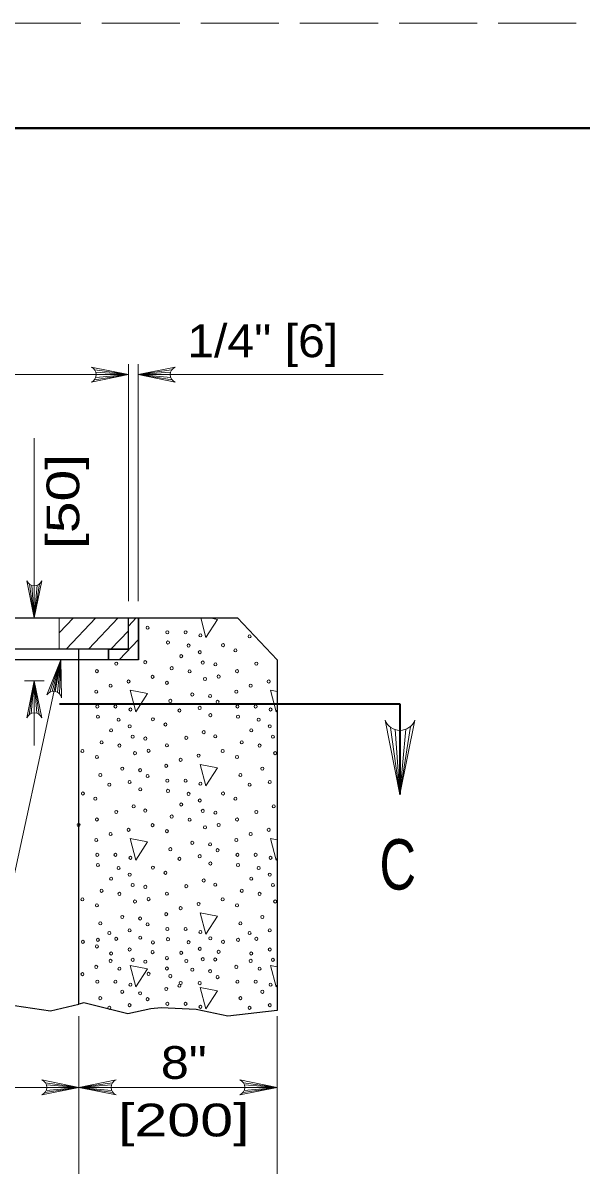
# Model space of a CAD drawing. Extents: x -410.5 to -376.5, y 1617.6 to 1661.6.
# Drawn here: x -391.36 to -388.7, y 1656.07 to 1661.56 of the extents above; entities that cross this region are included whole.
import ezdxf
from ezdxf.enums import TextEntityAlignment as Align

# ---------------------------------------------------------------- set-up
doc = ezdxf.new("R2010")
doc.units = 0
doc.header["$LTSCALE"] = 0.062
doc.linetypes.add('LONG_DASHED', pattern=[7.5, 6, -1.5])
doc.layers.add('1', color=7, linetype='Continuous', lineweight=13)

msp = doc.modelspace()

# ---------------------------------------------------------------- linework, layer by layer
at = {"layer": '1', "lineweight": 25}
for p, q in [((-408.45475, 1661.06183), (-376.95475, 1661.06183)), ((-391.90558, 1658.72817), (-390.8125, 1658.72817)), ((-390.85967, 1658.57825), (-390.85967, 1658.72817)), ((-390.8125, 1658.52825), (-390.8125, 1658.72817)), ((-390.85967, 1658.57825), (-391.4025, 1658.57825)), ((-390.8125, 1658.52825), (-391.4025, 1658.52825)), ((-391.09567, 1656.88817), (-391.09567, 1658.57825)), ((-390.95408, 1658.57825), (-390.95408, 1658.52825))]:
    msp.add_line(p, q, dxfattribs=at)
at = {"layer": '1'}
for p, q in [((-391.01992, 1659.90942), (-390.85967, 1659.887)), ((-390.85967, 1658.80683), (-390.85967, 1659.937)), ((-390.65383, 1659.90942), (-390.81408, 1659.887)), ((-390.81375, 1658.80683), (-390.81375, 1659.937)), ((-392.77792, 1659.887), (-390.85967, 1659.887)), ((-392.03408, 1659.887), (-390.86258, 1659.887)), ((-391.02183, 1659.86225), (-390.85967, 1659.887)), ((-391.01567, 1659.87258), (-390.85967, 1659.887)), ((-391.0145, 1659.89833), (-390.85967, 1659.887)), ((-391.01283, 1659.887), (-390.85967, 1659.887)), ((-390.65925, 1659.89833), (-390.81408, 1659.887)), ((-390.81408, 1659.887), (-389.647, 1659.887)), ((-390.66092, 1659.887), (-390.81408, 1659.887)), ((-390.65808, 1659.87258), (-390.81408, 1659.887)), ((-390.65192, 1659.86225), (-390.81408, 1659.887)), ((-391.30808, 1658.72817), (-391.30808, 1659.58383)), ((-391.3305, 1658.88833), (-391.30808, 1658.72817)), ((-391.31942, 1658.88292), (-391.30808, 1658.72817)), ((-391.28325, 1658.89025), (-391.30808, 1658.72817)), ((-391.29367, 1658.88417), (-391.30808, 1658.72817)), ((-391.30808, 1658.88133), (-391.30808, 1658.72817)), ((-391.30808, 1658.72817), (-391.11925, 1658.72817)), ((-391.19008, 1658.57825), (-391.19008, 1658.72817)), ((-391.19008, 1658.65608), (-391.12208, 1658.72808)), ((-391.15675, 1658.57833), (-391.01525, 1658.72808)), ((-391.05, 1658.57833), (-390.9085, 1658.72808)), ((-390.85967, 1658.6885), (-390.82225, 1658.72817)), ((-390.51508, 1658.72808), (-390.49042, 1658.63442)), ((-390.94325, 1658.57833), (-390.85967, 1658.66675)), ((-390.90425, 1658.52825), (-390.8125, 1658.62542)), ((-391.23483, 1658.37333), (-391.18092, 1658.52825)), ((-391.22358, 1658.3775), (-391.18092, 1658.52825)), ((-391.20883, 1658.37767), (-391.18092, 1658.52825)), ((-391.198, 1658.374), (-391.18092, 1658.52825)), ((-391.18808, 1658.36658), (-391.18092, 1658.52825)), ((-391.35525, 1658.42833), (-391.26083, 1658.42833)), ((-391.33283, 1658.26617), (-391.30808, 1658.42833)), ((-391.3225, 1658.27233), (-391.30808, 1658.42833)), ((-391.30808, 1658.42833), (-391.30808, 1658.11933)), ((-391.30808, 1658.27517), (-391.30808, 1658.42833)), ((-391.29675, 1658.2735), (-391.30808, 1658.42833)), ((-391.28567, 1658.26808), (-391.30808, 1658.42833)), ((-390.15167, 1658.37717), (-390.18367, 1658.3835)), ((-389.61125, 1658.2065), (-389.56642, 1657.886)), ((-389.51692, 1658.21033), (-389.56642, 1657.886)), ((-389.53767, 1658.198), (-389.56642, 1657.886)), ((-389.58908, 1658.19567), (-389.56642, 1657.886)), ((-389.56642, 1658.19233), (-389.56642, 1657.886)), ((-390.15175, 1657.6705), (-390.18367, 1657.67675)), ((-390.15167, 1657.06608), (-390.18367, 1657.07225)), ((-391.09567, 1656.07967), (-391.09567, 1656.82983)), ((-390.15167, 1656.07967), (-390.15167, 1656.82983)), ((-391.25592, 1656.51367), (-391.09567, 1656.49125)), ((-391.2505, 1656.50258), (-391.09567, 1656.49125)), ((-390.93542, 1656.51367), (-391.09567, 1656.49125)), ((-390.94083, 1656.50258), (-391.09567, 1656.49125)), ((-390.31192, 1656.51367), (-390.15167, 1656.49125)), ((-390.3065, 1656.50258), (-390.15167, 1656.49125)), ((-392.1675, 1656.49125), (-391.09567, 1656.49125)), ((-391.25783, 1656.4665), (-391.09567, 1656.49125)), ((-391.25167, 1656.47683), (-391.09567, 1656.49125)), ((-391.24883, 1656.49125), (-391.09567, 1656.49125)), ((-390.9425, 1656.49125), (-391.09567, 1656.49125)), ((-390.93967, 1656.47683), (-391.09567, 1656.49125)), ((-390.93358, 1656.4665), (-391.09567, 1656.49125)), ((-390.31383, 1656.4665), (-390.15167, 1656.49125)), ((-390.30767, 1656.47683), (-390.15167, 1656.49125)), ((-390.30483, 1656.49125), (-390.15167, 1656.49125))]:
    msp.add_line(p, q, dxfattribs=at)
at = {"layer": '1', "lineweight": 35}
for p, q in [((-391.188, 1658.31867), (-389.56642, 1658.31867)), ((-389.56642, 1658.31867), (-389.56642, 1657.886))]:
    msp.add_line(p, q, dxfattribs=at)
at = {"layer": '1', "linetype": 'LONG_DASHED'}
msp.add_lwpolyline([(-410.45475, 1639.56183), (-376.45475, 1639.56183), (-376.45475, 1661.56183), (-410.45475, 1661.56183)], close=True, dxfattribs=at)
at = {"layer": '1', "lineweight": 40}
msp.add_lwpolyline([(-408.45475, 1661.06183), (-376.95475, 1661.06183), (-376.95475, 1640.06183), (-408.45475, 1640.06183)], close=True, dxfattribs=at)
msp.add_lwpolyline([(-408.45475, 1661.06183), (-376.95475, 1661.06183), (-376.95475, 1640.06183), (-408.45475, 1640.06183)], close=True, dxfattribs=at)
at = {"layer": '1'}
for points in [[(-391.03667, 1659.85158), (-390.85967, 1659.887), (-391.03667, 1659.92242)], [(-390.63708, 1659.85158), (-390.81408, 1659.887), (-390.63708, 1659.92242)], [(-391.27267, 1658.90517), (-391.30808, 1658.72817), (-391.3435, 1658.90517)], [(-390.49042, 1658.63442), (-390.4355, 1658.72092), (-390.47292, 1658.72817)], [(-391.18092, 1658.52825), (-391.4595, 1657.24567), (-391.65833, 1657.24567)], [(-391.248, 1658.36067), (-391.18092, 1658.52825), (-391.17842, 1658.34775)], [(-391.3435, 1658.25133), (-391.30808, 1658.42833), (-391.27267, 1658.25133)], [(-390.18367, 1658.3835), (-390.15667, 1658.28108), (-390.15158, 1658.28892)], [(-389.49567, 1658.24), (-389.56642, 1657.886), (-389.63725, 1658.24)], [(-390.18367, 1657.67675), (-390.15667, 1657.57442), (-390.15167, 1657.58217)], [(-390.18367, 1657.07225), (-390.15667, 1656.96983), (-390.15167, 1656.97792)], [(-391.27267, 1656.45583), (-391.09567, 1656.49125), (-391.27267, 1656.52667)], [(-390.91867, 1656.45583), (-391.09567, 1656.49125), (-390.91867, 1656.52667)], [(-390.32867, 1656.45583), (-390.15167, 1656.49125), (-390.32867, 1656.52667)], [(-391.09567, 1656.49125), (-390.35633, 1656.49125), (-390.15167, 1656.49125)]]:
    msp.add_lwpolyline(points, dxfattribs=at)
at = {"layer": '1', "lineweight": 25}
msp.add_lwpolyline([(-390.95408, 1658.57825), (-390.85967, 1658.57825), (-390.85967, 1658.72817), (-390.8125, 1658.72817), (-390.8125, 1658.52825), (-390.95408, 1658.52825)], close=True, dxfattribs=at)
for points in [[(-390.8125, 1658.72817), (-390.3405, 1658.72817), (-390.15167, 1658.52825), (-390.15167, 1656.858)], [(-393.83325, 1656.87183), (-393.68983, 1656.83983), (-393.57033, 1656.87083), (-393.40175, 1656.85217), (-393.34308, 1656.855), (-393.2425, 1656.88925), (-393.18192, 1656.882), (-393.12783, 1656.87983), (-392.90825, 1656.84083), (-392.75167, 1656.88892), (-392.54808, 1656.86817), (-392.37933, 1656.90217), (-392.26933, 1656.909), (-392.08858, 1656.85375), (-391.91983, 1656.88475), (-391.69733, 1656.84675), (-391.53892, 1656.88275), (-391.48967, 1656.89375), (-391.23017, 1656.85558), (-391.09567, 1656.88817)], [(-390.15167, 1656.858), (-390.38608, 1656.83008), (-390.53658, 1656.86183), (-390.70333, 1656.87042), (-390.75258, 1656.86542), (-390.86258, 1656.8415), (-391.07275, 1656.89367), (-391.09567, 1656.88817)]]:
    msp.add_lwpolyline(points, dxfattribs=at)
at = {"layer": '1'}
for points in [[(-390.85117, 1658.3835), (-390.82417, 1658.28108), (-390.76917, 1658.3675)], [(-390.51742, 1658.03008), (-390.49042, 1657.92767), (-390.4355, 1658.01408)], [(-390.85117, 1657.67675), (-390.82417, 1657.57442), (-390.76917, 1657.66083)], [(-390.51742, 1657.32342), (-390.49042, 1657.221), (-390.4355, 1657.30742)], [(-390.85117, 1657.07225), (-390.82417, 1656.96983), (-390.76917, 1657.05625)], [(-390.51742, 1656.96708), (-390.49042, 1656.86467), (-390.4355, 1656.95117)]]:
    msp.add_lwpolyline(points, close=True, dxfattribs=at)
for centre, radius, start, end in [((-391.05096, 1659.88703), 0.0382, 292.08605, 67.91218), ((-390.62279, 1659.88703), 0.0382, 112.08782, 247.91395), ((-391.30811, 1658.91942), 0.0382, 202.08782, 337.91395), ((-391.21579, 1658.34016), 0.0382, 11.58076, 147.40689), ((-391.30803, 1658.23701), 0.0382, 22.08782, 157.91395), ((-389.56653, 1658.26863), 0.0764, 202.08782, 337.91395), ((-391.28698, 1656.49131), 0.0382, 292.08605, 67.91218), ((-390.90439, 1656.49131), 0.0382, 112.08782, 247.91395), ((-390.34298, 1656.49131), 0.0382, 292.08605, 67.91218)]:
    msp.add_arc(centre, radius, start, end, dxfattribs=at)
for centre, major_axis in [((-390.76879, 1658.68111), (0, -0.00756)), ((-390.67417, 1658.65914), (0, -0.00756)), ((-390.58762, 1658.65914), (0, 0.00756)), ((-390.51648, 1658.64483), (0, -0.00756)), ((-390.28301, 1658.64006), (0, 0.00756)), ((-390.6715, 1658.6105), (0, -0.00756)), ((-390.57321, 1658.59618), (0, 0.00756)), ((-390.40923, 1658.59807), (0, -0.00756)), ((-390.34977, 1658.57328), (0, -0.00756)), ((-390.60842, 1658.5456), (0, 0.00756)), ((-390.52009, 1658.56468), (0, 0.00756)), ((-391.01004, 1658.47398), (0, -0.00756)), ((-390.91782, 1658.51003), (0, -0.00756)), ((-390.77992, 1658.51668), (0, -0.00756)), ((-390.65376, 1658.48806), (0, 0.00756)), ((-390.56876, 1658.4731), (0, 0.00756)), ((-390.50563, 1658.51509), (0, 0.00756)), ((-390.44527, 1658.50643), (0, -0.00756)), ((-390.34253, 1658.47398), (0, -0.00756)), ((-390.25031, 1658.51003), (0, -0.00756)), ((-390.85924, 1658.42505), (0, -0.00756)), ((-390.74482, 1658.44701), (0, 0.00756)), ((-390.67629, 1658.41839), (0, 0.00756)), ((-390.49489, 1658.43682), (0, 0.00756)), ((-390.42998, 1658.44831), (0, -0.00756)), ((-390.19173, 1658.42505), (0, -0.00756)), ((-391.01332, 1658.3764), (0, -0.00756)), ((-390.9449, 1658.40502), (0, -0.00756)), ((-390.55552, 1658.36309), (0, 0.00756)), ((-390.47047, 1658.35573), (0, 0.00756)), ((-390.34582, 1658.3764), (0, -0.00756)), ((-390.2774, 1658.40502), (0, -0.00756)), ((-391.00793, 1658.30579), (0, -0.00756)), ((-390.92138, 1658.30579), (0, 0.00756)), ((-390.66005, 1658.33253), (0, 0.00756)), ((-390.52037, 1658.29914), (0, 0.00756)), ((-390.43504, 1658.32776), (0, -0.00756)), ((-390.34042, 1658.30579), (0, -0.00756)), ((-390.25387, 1658.30579), (0, 0.00756)), ((-391.00526, 1658.25715), (0, -0.00756)), ((-390.85023, 1658.29148), (0, -0.00756)), ((-390.74298, 1658.24472), (0, -0.00756)), ((-390.61677, 1658.28671), (0, 0.00756)), ((-390.46958, 1658.26445), (0, -0.00756)), ((-390.33775, 1658.25715), (0, -0.00756)), ((-390.18272, 1658.29148), (0, -0.00756)), ((-390.94218, 1658.19225), (0, 0.00756)), ((-390.90697, 1658.24283), (0, 0.00756)), ((-390.85385, 1658.21133), (0, 0.00756)), ((-390.68352, 1658.21993), (0, -0.00756)), ((-390.27467, 1658.19225), (0, 0.00756)), ((-390.23946, 1658.24283), (0, 0.00756)), ((-390.18634, 1658.21133), (0, 0.00756)), ((-390.98751, 1658.13471), (0, 0.00756)), ((-390.83938, 1658.16174), (0, 0.00756)), ((-390.77903, 1658.15308), (0, -0.00756)), ((-390.58406, 1658.15668), (0, -0.00756)), ((-390.50112, 1658.18335), (0, -0.00756)), ((-390.44616, 1658.16333), (0, -0.00756)), ((-390.32001, 1658.13471), (0, 0.00756)), ((-390.17187, 1658.16174), (0, 0.00756)), ((-391.07857, 1658.09366), (0, 0.00756)), ((-390.90252, 1658.11975), (0, 0.00756)), ((-390.82865, 1658.08347), (0, 0.00756)), ((-390.76373, 1658.09496), (0, -0.00756)), ((-390.67629, 1658.12063), (0, -0.00756)), ((-390.41106, 1658.09366), (0, 0.00756)), ((-390.23501, 1658.11975), (0, 0.00756)), ((-390.16114, 1658.08347), (0, 0.00756)), ((-391.01004, 1658.06504), (0, 0.00756)), ((-390.61115, 1658.05167), (0, -0.00756)), ((-390.52549, 1658.0717), (0, -0.00756)), ((-390.34253, 1658.06504), (0, 0.00756)), ((-390.9938, 1657.97918), (0, 0.00756)), ((-390.88928, 1658.00974), (0, 0.00756)), ((-390.80423, 1658.00238), (0, 0.00756)), ((-390.76879, 1657.97441), (0, -0.00756)), ((-390.67957, 1658.02305), (0, -0.00756)), ((-390.32629, 1657.97918), (0, 0.00756)), ((-390.22177, 1658.00974), (0, 0.00756)), ((-390.95052, 1657.93336), (0, 0.00756)), ((-390.85412, 1657.94579), (0, 0.00756)), ((-390.67417, 1657.95244), (0, -0.00756)), ((-390.58762, 1657.95244), (0, 0.00756)), ((-390.51648, 1657.93813), (0, -0.00756)), ((-390.28301, 1657.93336), (0, 0.00756)), ((-390.18662, 1657.94579), (0, 0.00756)), ((-391.07674, 1657.89137), (0, -0.00756)), ((-391.01727, 1657.86658), (0, -0.00756)), ((-390.80334, 1657.9111), (0, -0.00756)), ((-390.6715, 1657.9038), (0, -0.00756)), ((-390.57321, 1657.88949), (0, 0.00756)), ((-390.40923, 1657.89137), (0, -0.00756)), ((-390.34977, 1657.86658), (0, -0.00756)), ((-390.83488, 1657.83), (0, -0.00756)), ((-390.77992, 1657.80998), (0, -0.00756)), ((-390.60842, 1657.8389), (0, 0.00756)), ((-390.52009, 1657.85798), (0, 0.00756)), ((-390.50563, 1657.80839), (0, 0.00756)), ((-390.16737, 1657.83), (0, -0.00756)), ((-391.01004, 1657.76728), (0, -0.00756)), ((-390.91782, 1657.80333), (0, -0.00756)), ((-390.65376, 1657.78136), (0, 0.00756)), ((-390.56876, 1657.7664), (0, 0.00756)), ((-390.44527, 1657.79973), (0, -0.00756)), ((-390.34253, 1657.76728), (0, -0.00756)), ((-390.25031, 1657.80333), (0, -0.00756)), ((-391.09749, 1657.74161), (0, -0.00756)), ((-390.9449, 1657.69832), (0, -0.00756)), ((-390.85924, 1657.71835), (0, -0.00756)), ((-390.74482, 1657.74031), (0, 0.00756)), ((-390.67629, 1657.71169), (0, 0.00756)), ((-390.49489, 1657.73012), (0, 0.00756)), ((-390.42998, 1657.74161), (0, -0.00756)), ((-390.2774, 1657.69832), (0, -0.00756)), ((-390.19173, 1657.71835), (0, -0.00756)), ((-391.01332, 1657.6697), (0, -0.00756)), ((-390.55552, 1657.65639), (0, 0.00756)), ((-390.47047, 1657.64903), (0, 0.00756)), ((-390.34582, 1657.6697), (0, -0.00756)), ((-391.00793, 1657.59909), (0, -0.00756)), ((-390.92138, 1657.59909), (0, 0.00756)), ((-390.85023, 1657.58478), (0, -0.00756)), ((-390.66005, 1657.62583), (0, 0.00756)), ((-390.52037, 1657.59244), (0, 0.00756)), ((-390.43504, 1657.62106), (0, -0.00756)), ((-390.34042, 1657.59909), (0, -0.00756)), ((-390.25387, 1657.59909), (0, 0.00756)), ((-390.18272, 1657.58478), (0, -0.00756)), ((-391.00526, 1657.55045), (0, -0.00756)), ((-390.90697, 1657.53614), (0, 0.00756)), ((-390.74298, 1657.53802), (0, -0.00756)), ((-390.61677, 1657.58001), (0, 0.00756)), ((-390.46958, 1657.55775), (0, -0.00756)), ((-390.33775, 1657.55045), (0, -0.00756)), ((-390.23946, 1657.53614), (0, 0.00756)), ((-390.94218, 1657.48555), (0, 0.00756)), ((-390.85385, 1657.50463), (0, 0.00756)), ((-390.68352, 1657.51323), (0, -0.00756)), ((-390.50112, 1657.47665), (0, -0.00756)), ((-390.27467, 1657.48555), (0, 0.00756)), ((-390.18634, 1657.50463), (0, 0.00756)), ((-390.98751, 1657.42801), (0, 0.00756)), ((-390.83938, 1657.45504), (0, 0.00756)), ((-390.77903, 1657.44638), (0, -0.00756)), ((-390.58406, 1657.44998), (0, -0.00756)), ((-390.44616, 1657.45663), (0, -0.00756)), ((-390.32001, 1657.42801), (0, 0.00756)), ((-390.17187, 1657.45504), (0, 0.00756)), ((-391.07857, 1657.38696), (0, 0.00756)), ((-390.90252, 1657.41305), (0, 0.00756)), ((-390.82865, 1657.37677), (0, 0.00756)), ((-390.76373, 1657.38826), (0, -0.00756)), ((-390.67629, 1657.41394), (0, -0.00756)), ((-390.52549, 1657.365), (0, -0.00756)), ((-390.41106, 1657.38696), (0, 0.00756)), ((-390.23501, 1657.41305), (0, 0.00756)), ((-390.16114, 1657.37677), (0, 0.00756)), ((-391.01004, 1657.35834), (0, 0.00756)), ((-390.67957, 1657.31635), (0, -0.00756)), ((-390.61115, 1657.34497), (0, -0.00756)), ((-390.34253, 1657.35834), (0, 0.00756)), ((-390.9938, 1657.27248), (0, 0.00756)), ((-390.88928, 1657.30304), (0, 0.00756)), ((-390.80423, 1657.29568), (0, 0.00756)), ((-390.76879, 1657.26771), (0, -0.00756)), ((-390.32629, 1657.27248), (0, 0.00756)), ((-390.22177, 1657.30304), (0, 0.00756)), ((-390.95052, 1657.22666), (0, 0.00756)), ((-390.85412, 1657.23909), (0, 0.00756)), ((-390.80334, 1657.2044), (0, -0.00756)), ((-390.67417, 1657.24574), (0, -0.00756)), ((-390.58762, 1657.24574), (0, 0.00756)), ((-390.51648, 1657.23143), (0, -0.00756)), ((-390.46958, 1657.20143), (0, -0.00756)), ((-390.28301, 1657.22666), (0, 0.00756)), ((-390.18662, 1657.23909), (0, 0.00756)), ((-391.07674, 1657.18467), (0, -0.00756)), ((-391.01004, 1657.16278), (0, -0.00756)), ((-391.00526, 1657.19412), (0, -0.00756)), ((-390.91782, 1657.19882), (0, -0.00756)), ((-390.85385, 1657.14831), (0, 0.00756)), ((-390.74299, 1657.1817), (0, -0.00756)), ((-390.6715, 1657.1971), (0, -0.00756)), ((-390.57321, 1657.18279), (0, 0.00756)), ((-390.52009, 1657.15128), (0, 0.00756)), ((-390.40923, 1657.18467), (0, -0.00756)), ((-390.33775, 1657.19412), (0, -0.00756)), ((-390.25031, 1657.19882), (0, -0.00756)), ((-390.18634, 1657.14831), (0, 0.00756)), ((-390.94491, 1657.09382), (0, -0.00756)), ((-390.94218, 1657.12923), (0, 0.00756)), ((-390.83938, 1657.09872), (0, 0.00756)), ((-390.74482, 1657.13581), (0, 0.00756)), ((-390.67629, 1657.10719), (0, 0.00756)), ((-390.60842, 1657.1322), (0, 0.00756)), ((-390.58406, 1657.09366), (0, -0.00756)), ((-390.50563, 1657.10169), (0, 0.00756)), ((-390.44617, 1657.10031), (0, -0.00756)), ((-390.42998, 1657.1371), (0, -0.00756)), ((-390.2774, 1657.09382), (0, -0.00756)), ((-390.27467, 1657.12923), (0, 0.00756)), ((-390.17188, 1657.09872), (0, 0.00756)), ((-391.01333, 1657.0652), (0, -0.00756)), ((-390.90252, 1657.05673), (0, 0.00756)), ((-390.77903, 1657.09006), (0, -0.00756)), ((-390.67629, 1657.05761), (0, -0.00756)), ((-390.55553, 1657.05189), (0, 0.00756)), ((-390.47047, 1657.04453), (0, 0.00756)), ((-390.34582, 1657.0652), (0, -0.00756)), ((-390.23501, 1657.05673), (0, 0.00756)), ((-391.07858, 1657.03064), (0, 0.00756)), ((-391.00793, 1656.99459), (0, -0.00756)), ((-390.92138, 1656.99459), (0, 0.00756)), ((-390.76373, 1657.03194), (0, -0.00756)), ((-390.66005, 1657.02132), (0, 0.00756)), ((-390.61115, 1656.98865), (0, -0.00756)), ((-390.52037, 1656.98793), (0, 0.00756)), ((-390.43504, 1657.01655), (0, -0.00756)), ((-390.34042, 1656.99459), (0, -0.00756)), ((-390.25387, 1656.99459), (0, 0.00756)), ((-390.88928, 1656.94672), (0, 0.00756)), ((-390.85023, 1656.98028), (0, -0.00756)), ((-390.80423, 1656.93936), (0, 0.00756)), ((-390.67957, 1656.96003), (0, -0.00756)), ((-390.61677, 1656.9755), (0, 0.00756)), ((-390.22177, 1656.94672), (0, 0.00756)), ((-390.18272, 1656.98028), (0, -0.00756)), ((-390.9938, 1656.91616), (0, 0.00756)), ((-390.85413, 1656.88276), (0, 0.00756)), ((-390.7688, 1656.91139), (0, -0.00756)), ((-390.67418, 1656.88942), (0, -0.00756)), ((-390.58762, 1656.88942), (0, 0.00756)), ((-390.51648, 1656.87511), (0, -0.00756)), ((-390.32629, 1656.91616), (0, 0.00756)), ((-390.18662, 1656.88276), (0, 0.00756)), ((-390.95052, 1656.87034), (0, 0.00756)), ((-390.28302, 1656.87034), (0, 0.00756))]:
    msp.add_ellipse(centre, major_axis=major_axis, ratio=0.944543, dxfattribs=at)

# ---------------------------------------------------------------- texts
at = {"layer": '1', "width": 1.1}
msp.add_text('1/4" [6]', height=0.156, dxfattribs=at).set_placement((-390.57975, 1659.96992))
at = {"layer": '1', "width": 1.3}
msp.add_text('[50]', height=0.156, rotation=90, dxfattribs=at).set_placement((-391.09392, 1659.28271), align=Align.CENTER)
at = {"layer": '1'}
for s, height, width, p in [('C', 0.24, 0.75, (-389.57692, 1657.43358)), ('8"', 0.156, 1.15, (-390.59608, 1656.53175)), ('[200]', 0.156, 1.35, (-390.59608, 1656.25775))]:
    msp.add_text(s, height=height, dxfattribs=dict(at, width=width)).set_placement(p, align=Align.CENTER)

doc.saveas('drawing.dxf')
